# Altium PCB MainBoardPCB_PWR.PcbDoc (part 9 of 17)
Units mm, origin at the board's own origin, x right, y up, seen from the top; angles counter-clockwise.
Board outline 333.63 x 349.38 mm, 16 copper layers (L1, L2 (GND), L3 (Sign), L4 (GND), L5 (Sign), L6 (PWR/GND), L7(PWR/GND), L8 (PWR/GND), L9 (PWR/GND), L10 (PWR/GND), L11 (PWR/GND), L12 (Sign), L13 (GND), L14 (Sign), L15 (GND), L16), stack 2.503 mm thick; 2187 components, 1615 nets, 7987 pads, 1695 vias.
Unrouted connection lines stored in the file: 4757.
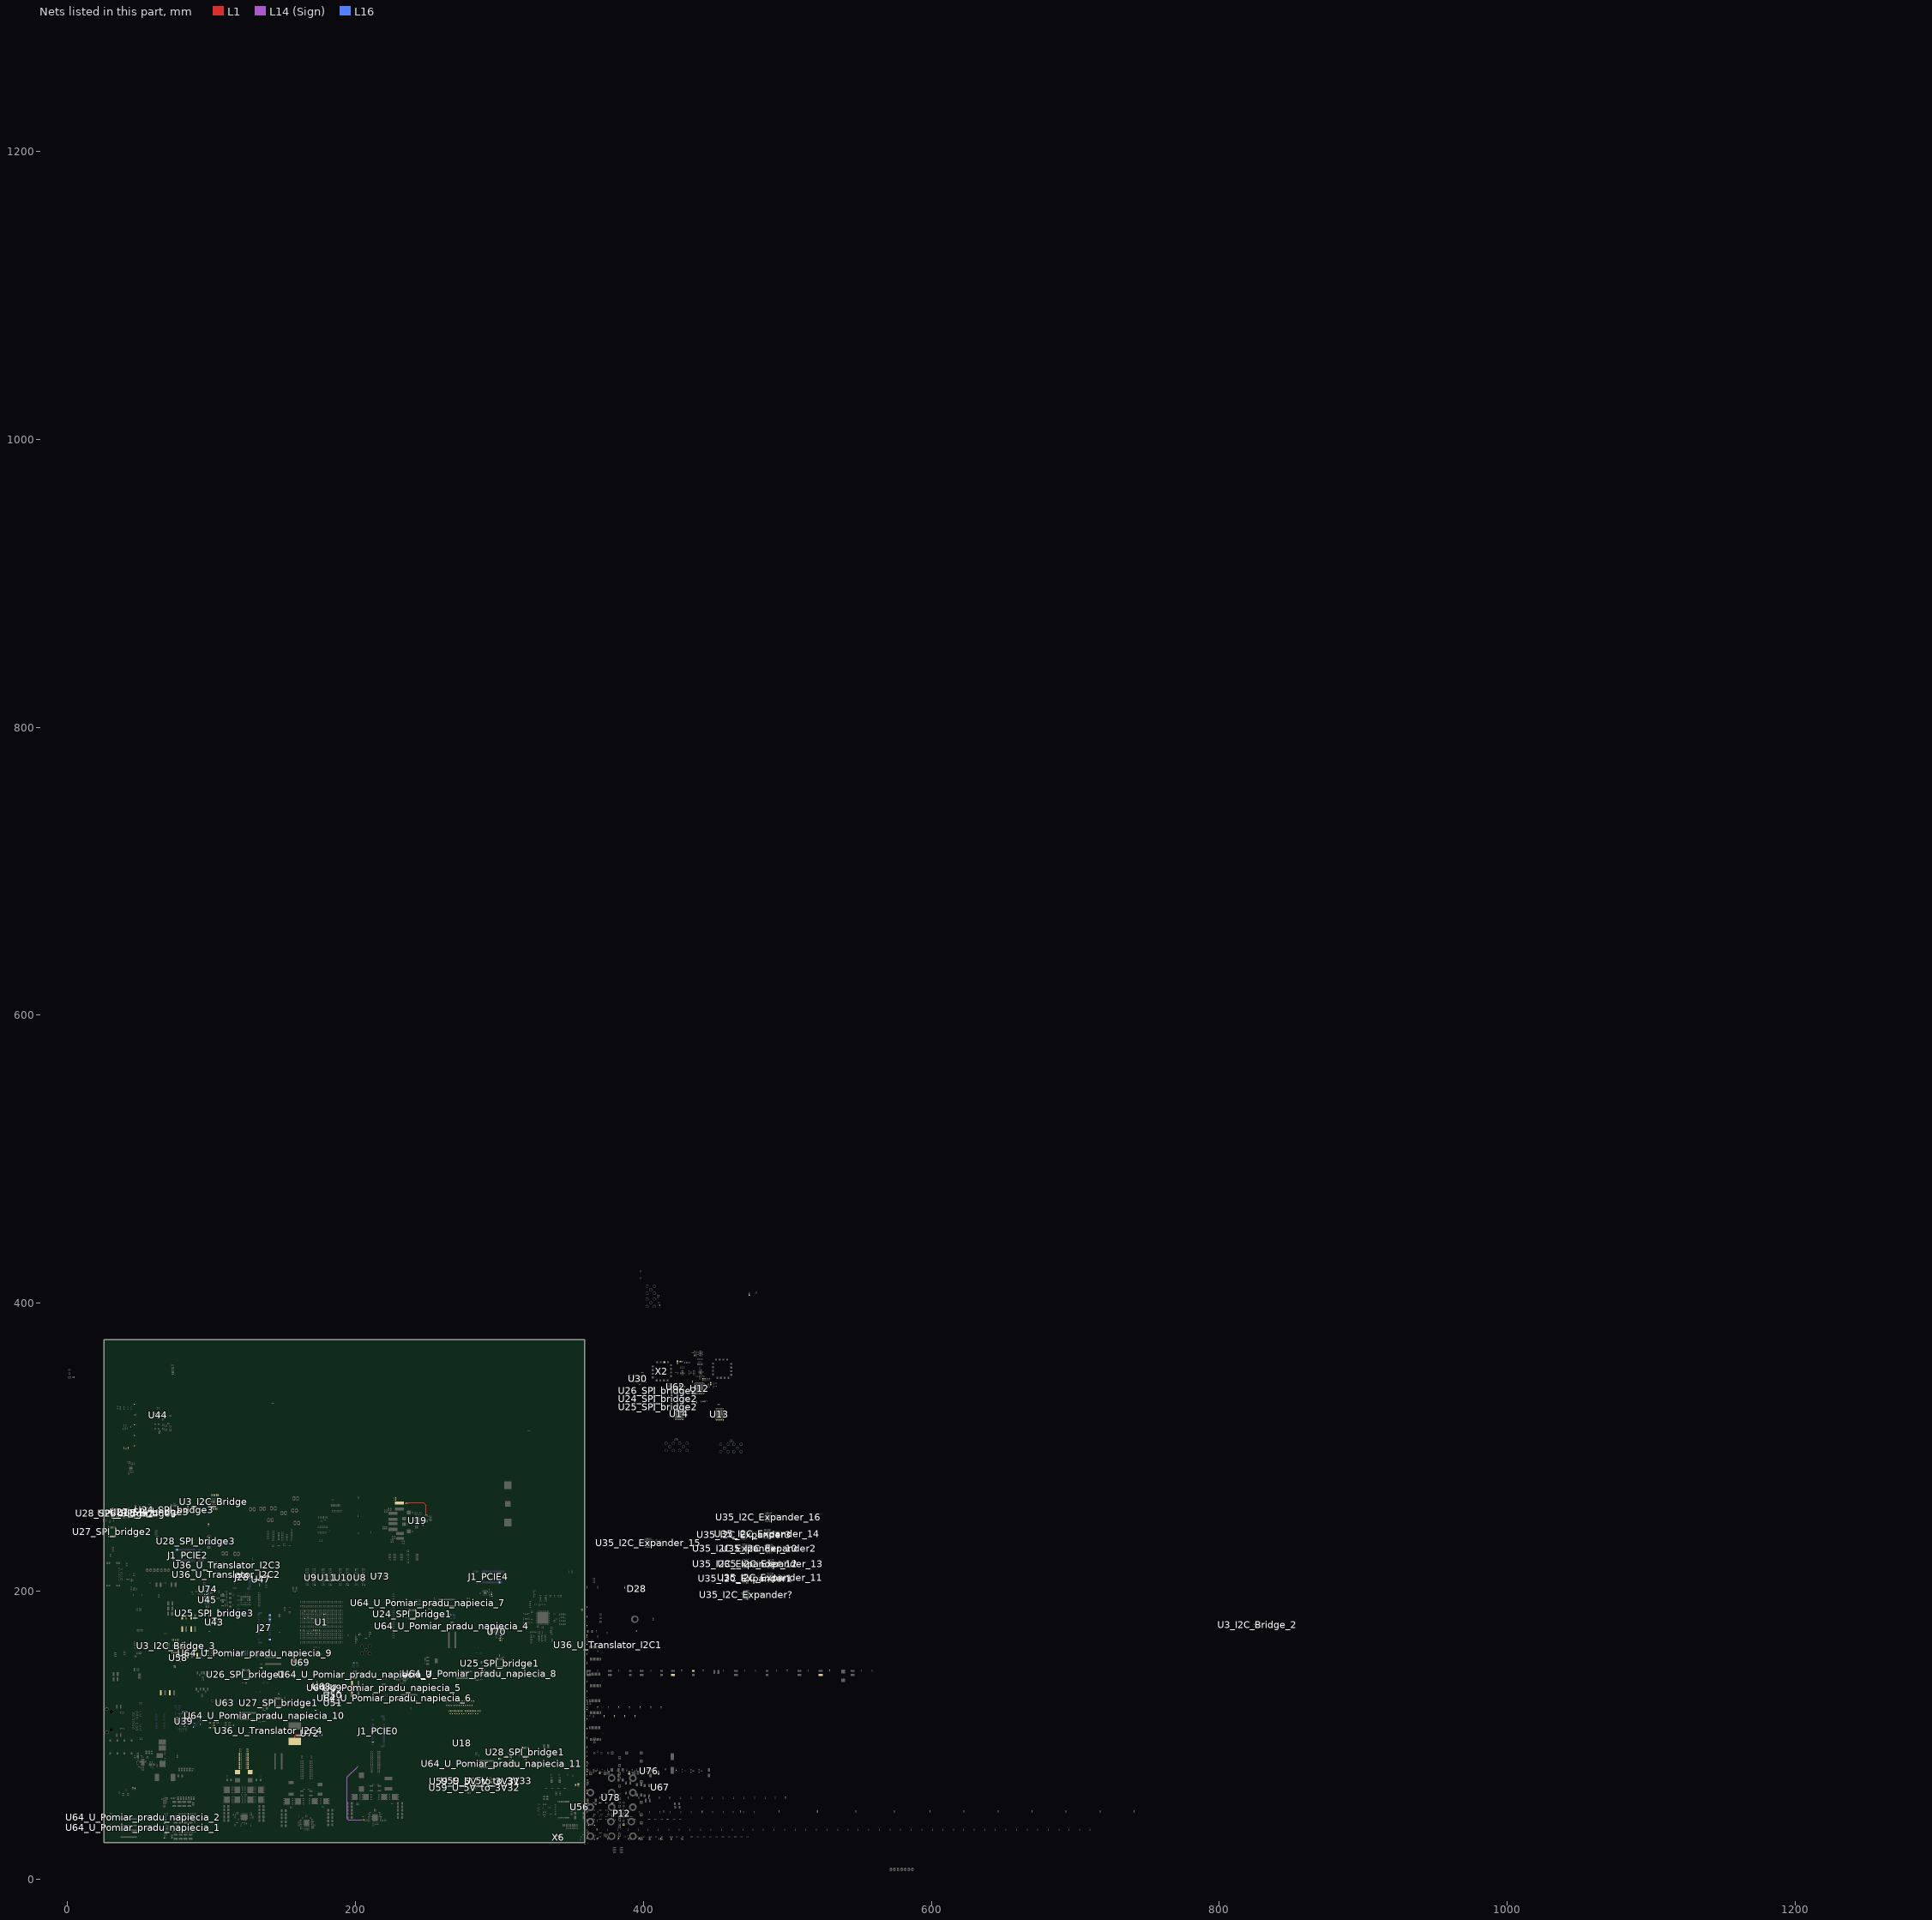
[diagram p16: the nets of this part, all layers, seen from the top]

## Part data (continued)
R600 R601: library part Resistor, Case Code (Imperial)=0402, Case Code (Metric)=1005, Manufacturer=Yageo, Manufacturer Part Number=RC0402JR-070RL, Max Operating Temperature=155°C, Max Power Dissipation=63mW, Min Operating Temperature=-55°C, Package Quantity=1, Power Rating=62.5mW, Supplier Part Number 1=311-0.0JRCT-ND, Temperature Coefficient=200ppm/°C, Tolerance=5%, Voltage Rating=50V
R602 R603 R604 R605 R606 R608 R609: library part Resistor, "RES 10K OHM 0.1% 1/16W 0402", Case/Package=0402, Case Code (Metric)=1005, Manufacturer="Stackpole Electronics", Manufacturer Part Number=RNCF0402BTE10K0, Max Operating Temperature=155°C, Max Power Dissipation=63mW, Min Operating Temperature=-55°C, Package Quantity=10000, Supplier Part Number 1=RNCF0402BTE10K0CT-ND, Temperature Coefficient=25ppm/°C, Tolerance=0.1%
R610 R611: library part Resistor, Case/Package=0402, Case Code (Metric)=1005, Manufacturer=Yageo, Manufacturer Part Number=RC0402FR-071K33L, Max Operating Temperature=155°C, Max Power Dissipation=63mW, Min Operating Temperature=-55°C, Package Quantity=1, Power Rating=62.5mW, Supplier Part Number 1=311-1.33KLRCT-ND, Temperature Coefficient=100ppm/°C, Tolerance=1%, Voltage Rating=50V
R612 R614: library part Resistor, Case/Package=0402, Manufacturer="Vishay BCcomponents", Manufacturer Part Number=MCS04020C2203FE000, Max Operating Temperature=125°C, Min Operating Temperature=-55°C, Supplier Part Number 1=749-1566-1-ND, Temperature Coefficient=50ppm/°C, Tolerance=1%
R613 R616: library part Resistor, Case/Package=1206, Case Code (Metric)=3216, Manufacturer="Vishay Dale", Manufacturer Part Number=CRCW12062R40FKEAHP, Max Operating Temperature=155°C, Max Power Dissipation=500mW, Min Operating Temperature=-55°C, Supplier Part Number 1=541-2.40UCT-ND, Temperature Coefficient=100ppm/°C, Tolerance=1%
R615: library part Resistor, Case/Package=0402, Case Code (Metric)=1005, Manufacturer=Yageo, Manufacturer Part Number=RC0402FR-0710KL, Max Operating Temperature=155°C, Min Operating Temperature=-55°C, Power Rating=62.5mW, Supplier Part Number 1=311-10.0KLRDKR-ND, Temperature Coefficient=100ppm/°C, Tolerance=1%, Voltage Rating=50V
R617: "RES 0.004 OHM 1% 7W 5931", Case/Package=5931, Manufacturer=Yageo, Max Operating Temperature=170°C, Max Power Dissipation=7W, Min Operating Temperature=-65°C, Resistance=4mR, Supplier Part Number 1=YAG4096CT-ND, Temperature Coefficient=75ppm/°C, Tolerance=1%
R619: library part Resistor, Case/Package=0402, Case Code (Metric)=1005, Manufacturer="Stackpole Electronics", Manufacturer Part Number=RMCF0402FT1K91, Max Operating Temperature=155°C, Max Power Dissipation=63mW, Min Operating Temperature=-55°C, Supplier Part Number 1=RMCF0402FT1K91CT-ND, Temperature Coefficient=100ppm/°C, Tolerance=1%
R620: library part Resistor, Case/Package=0402, Case Code (Metric)=1005, Manufacturer=Yageo, Manufacturer Part Number=RC0402FR-072KL, Max Operating Temperature=155°C, Max Power Dissipation=63mW, Min Operating Temperature=-55°C, Package Quantity=1, Supplier Part Number 1=311-2KLRCT-ND, Temperature Coefficient=100ppm/°C, Tolerance=1%, Voltage Rating=50V
R621: library part Resistor, Case/Package=0402, Case Code (Metric)=1005, Manufacturer="Stackpole Electronics", Manufacturer Part Number=RMCF0402FT147K, Max Operating Temperature=155°C, Max Power Dissipation=63mW, Min Operating Temperature=-55°C, Temperature Coefficient=100ppm/°C, Tolerance=1%
R622: library part Resistor, Case/Package=0402, Case Code (Metric)=1005, Manufacturer="Stackpole Electronics", Manufacturer Part Number=RMCF0402FT340K, Max Operating Temperature=155°C, Max Power Dissipation=63mW, Min Operating Temperature=-55°C, Supplier Part Number 1=RMCF0402FT340KCT-ND, Temperature Coefficient=100ppm/°C, Tolerance=1%
R623: library part Resistor, Case/Package=0402, Case Code (Metric)=1005, Manufacturer=Panasonic, Manufacturer Part Number=ERA-2AEB1431X, Max Operating Temperature=155°C, Max Power Dissipation=63mW, Min Operating Temperature=-55°C, Package Quantity=1, Power Rating=62.5mW, Supplier Part Number 1=P1.43KDCCT-ND, Temperature Coefficient=25ppm/°C, Tolerance=0.1%, Voltage Rating=50V
R624: library part Resistor, Case/Package=0402, Case Code (Metric)=1005, Manufacturer=Panasonic, Manufacturer Part Number=ERJ-2RKF1502X, Max Operating Temperature=155°C, Max Power Dissipation=100mW, Min Operating Temperature=-55°C, Package Quantity=1, Supplier Part Number 1=P15.0KLDKR-ND, Temperature Coefficient=100ppm/°C, Tolerance=1%, Voltage Rating=50V
R625: library part Resistor, "Thick Film Resistors - SMD 1.4K OHM 1%", Case/Package=0402, Case Code (Metric)=1005, Manufacturer=Yageo, Manufacturer Part Number=RC0402FR-071K4L, Max Operating Temperature=155°C, Max Power Dissipation=63mW, Min Operating Temperature=-55°C, Power Rating=62.5mW, Supplier Part Number 1=YAG3039CT-ND, Temperature Coefficient=100ppm/°C, Tolerance=1%, Voltage Rating=50V
R626: library part Resistor, Case/Package=0402, Manufacturer="Vishay BCcomponents", Manufacturer Part Number=MCS04020C2003FE000, Max Operating Temperature=125°C, Min Operating Temperature=-55°C, Supplier Part Number 1=749-1562-1-ND, Temperature Coefficient=50ppm/°C, Tolerance=1%
R627: library part Resistor, Case/Package=0402, Case Code (Metric)=1005, Manufacturer=Yageo, Manufacturer Part Number=RC0402FR-0710K5L, Max Operating Temperature=155°C, Max Power Dissipation=63mW, Min Operating Temperature=-55°C, Power Rating=62.5mW, Supplier Part Number 1=YAG2951CT-ND, Temperature Coefficient=100ppm/°C, Tolerance=1%, Voltage Rating=50V
R628: library part Resistor, Case/Package=0402, Case Code (Metric)=1005, Manufacturer="Stackpole Electronics", Manufacturer Part Number=RMCF0402FT750K, Max Operating Temperature=155°C, Max Power Dissipation=63mW, Min Operating Temperature=-55°C, Supplier Part Number 1=RMCF0402FT750KCT-ND, Temperature Coefficient=100ppm/°C, Tolerance=1%
R631: library part Resistor, Case/Package=0402, Case Code (Metric)=1005, Manufacturer="Stackpole Electronics", Manufacturer Part Number=RMCF0402FT5K90, Max Operating Temperature=155°C, Max Power Dissipation=63mW, Min Operating Temperature=-55°C, Supplier Part Number 1=RMCF0402FT5K90CT-ND, Temperature Coefficient=100ppm/°C, Tolerance=1%
R632 R633 R634 R646 R690: library part Resistor, Case/Package=0402, Case Code (Metric)=1005, Manufacturer 1=Panasonic, Manufacturer Part Number 1=ERA-2AED104X, Max Operating Temperature=155°C, Max Power Dissipation=63mW, Min Operating Temperature=-55°C, Package Quantity=10000, Supplier Part Number 1=P100KDECT-ND, Temperature Coefficient=25ppm/°C, Tolerance=0.5%, Voltage Rating=25V
R644: library part Resistor, Case/Package=0402, Case Code (Metric)=1005, Manufacturer=Vishay, Manufacturer Part Number=CRCW04029K10FKED, Max Operating Temperature=155°C, Max Power Dissipation=63mW, Min Operating Temperature=-55°C, Package Quantity=10, Supplier Part Number 1=541-9.10KLCT-ND, Temperature Coefficient=100ppm/°C, Tolerance=1%, Voltage Rating=50V
R645: library part Resistor, Case/Package=0402, Case Code (Metric)=1005, Manufacturer=Panasonic, Manufacturer Part Number=ERA-2AED133X, Max Operating Temperature=155°C, Max Power Dissipation=63mW, Min Operating Temperature=-55°C, Package Quantity=1, Power Rating=62.5mW, Supplier Part Number 1=P13KDECT-ND, Temperature Coefficient=25ppm/°C, Tolerance=0.5%
R647: library part Resistor, "RES SMD 100K OHM 1% 1/16W 0402", Case Code (Imperial)=0402, Case Code (Metric)=1005, Manufacturer=Yageo, Manufacturer Part Number=RC0402FR-07100KL, Max Operating Temperature=155°C, Max Power Dissipation=63mW, Min Operating Temperature=-55°C, Package Quantity=1, Supplier Part Number 1=311-100KLRDKR-ND, Temperature Coefficient=100ppm/°C, Tolerance=1%, Voltage Rating=50V
R648: library part Resistor, "RES SMD 2 OHM 5% 1/16W 0402", Case Code (Imperial)=0402, Case Code (Metric)=1005, Manufacturer=Yageo, Manufacturer Part Number=RC0402JR-072RL, Max Operating Temperature=155°C, Min Operating Temperature=-55°C, Package Quantity=10000, Power Rating=62.5mW, Supplier Part Number 1=311-2.0JRCT-ND, Temperature Coefficient=200ppm/°C, Tolerance=5%, Voltage Rating=50V
R650: library part Resistor, "RES SMD 100M OHM 5% 1/16W 0402", Case Code (Imperial)=0402, Case Code (Metric)=1005, Manufacturer="Stackpole Electronics", Manufacturer Part Number=HMC0402JT100M, Max Operating Temperature=125°C, Max Power Dissipation=63mW, Min Operating Temperature=-55°C, Supplier Part Number 1=HMC0402JT100MCT-ND, Temperature Coefficient=400ppm/°C, Tolerance=5%
R652: library part Resistor, "RES SMD 1M OHM 1% 1/16W 0402", Case Code (Imperial)=0402, Case Code (Metric)=1005, Manufacturer=Yageo, Manufacturer Part Number=RC0402FR-071ML, Max Operating Temperature=155°C, Min Operating Temperature=-55°C, Power Rating=63mW, Supplier Part Number 1=311-1.00MLRDKR-ND, Temperature Coefficient=100ppm/°C, Tolerance=1%, Voltage Rating=50V
R653: library part Resistor, "RES SMD 20 OHM 5% 1/5W 0402", Case Code (Imperial)=0402, Case Code (Metric)=1005, Manufacturer=Rohm, Manufacturer Part Number=ESR01MZPJ200, Max Operating Temperature=155°C, Max Power Dissipation=200mW, Min Operating Temperature=-55°C, Package Quantity=1, Supplier Part Number 1=RHM1011CT-ND, Temperature Coefficient=200ppm/°C, Tolerance=5%
R666: library part Resistor, "RES 0.012 OHM 1% 1/2W 1206", Case/Package=1206, Case Code (Metric)=3216, Manufacturer="Stackpole Electronics", Manufacturer Part Number=CSR1206FK12L0, Max Operating Temperature=155°C, Max Power Dissipation=500mW, Min Operating Temperature=-55°C, Supplier Part Number 1=CSR1206FK12L0CT-ND, Temperature Coefficient=100ppm/°C, Tolerance=1%
R667: library part Resistor, "RES SMD 24.9KOHM 0.1% 1/16W 0402", Case/Package=0402, Case Code (Metric)=1005, Manufacturer=Panasonic, Manufacturer Part Number=ERA-2AEB2492X, Max Operating Temperature=155°C, Max Power Dissipation=63mW, Min Operating Temperature=-55°C, Package Quantity=1, Supplier Part Number 1=P24.9KDCCT-ND, Temperature Coefficient=25ppm/°C, Tolerance=0.1%, Voltage Rating=25V, Voltage Rating (DC)=50V
R671 R673: library part Resistor, Case/Package=0402, Case Code (Metric)=1005, Manufacturer=Panasonic, Manufacturer Part Number=ERA-2AEB1871X, Max Operating Temperature=155°C, Max Power Dissipation=63mW, Min Operating Temperature=-55°C, Package Quantity=10000, Power Rating=62.5mW, Supplier Part Number 1=P1.87KDCCT-ND, Temperature Coefficient=25ppm/°C, Tolerance=0.1%
R672: library part Resistor, Case/Package=0402, Case Code (Metric)=1005, Manufacturer=Panasonic, Manufacturer Part Number=ERA-2AEB152X, Max Operating Temperature=155°C, Max Power Dissipation=63mW, Min Operating Temperature=-55°C, Package Quantity=10000, Supplier Part Number 1=P1.5KDCCT-ND, Temperature Coefficient=25ppm/°C, Tolerance=0.1%, Voltage Rating=25V
R674: library part Resistor, Case/Package=0402, Case Code (Metric)=1005, Manufacturer=Panasonic, Manufacturer Part Number=ERA-2AEB153X, Max Operating Temperature=155°C, Max Power Dissipation=63mW, Min Operating Temperature=-55°C, Package Quantity=1, Supplier Part Number 1=P15KDCCT-ND, Temperature Coefficient=25ppm/°C, Tolerance=0.1%, Voltage Rating=25V
R676: library part Resistor, "RES SMD 20K OHM 1% 1/16W 0402", Case/Package=0402, Case Code (Metric)=1005, Manufacturer=Vishay, Manufacturer Part Number=CRCW040220K0FKED, Max Operating Temperature=155°C, Max Power Dissipation=63mW, Min Operating Temperature=-55°C, Package Quantity=10, Supplier Part Number 1=51X8496, Temperature Coefficient=100ppm/°C, Tolerance=1%, Voltage Rating=50V
R682: library part Resistor, Case/Package=0402, Case Code (Metric)=1005, Manufacturer 1=Yageo, Manufacturer Part Number 1=RC0402FR-077K5L, Max Operating Temperature=155°C, Max Power Dissipation=63mW, Min Operating Temperature=-55°C, Package Quantity=1, Supplier Part Number 1=311-7.50KLRCT-ND, Temperature Coefficient=100ppm/°C, Tolerance=1%, Voltage Rating=50V
R684: library part Resistor, Case/Package=0402, Case Code (Metric)=1005, Manufacturer 1=Yageo, Manufacturer Part Number 1=RC0402FR-077K15L, Max Operating Temperature=155°C, Max Power Dissipation=63mW, Min Operating Temperature=-55°C, Power Rating=62.5mW, Supplier Part Number 1=YAG3235CT-ND, Temperature Coefficient=100ppm/°C, Tolerance=1%, Voltage Rating=50V
R685: library part Resistor, Case/Package=0402, Case Code (Metric)=1005, Manufacturer 1=Yageo, Manufacturer Part Number 1=RC0402FR-075K9L, Max Operating Temperature=155°C, Max Power Dissipation=63mW, Min Operating Temperature=-55°C, Power Rating=62.5mW, Supplier Part Number 1=YAG3197CT-ND, Temperature Coefficient=100ppm/°C, Tolerance=1%, Voltage Rating=50V
R686: library part Resistor, Case/Package=0402, Case Code (Metric)=1005, Manufacturer=Yageo, Manufacturer Part Number=RC0402FR-07412KL, Max Operating Temperature=155°C, Max Power Dissipation=63mW, Min Operating Temperature=-55°C, Power Rating=62.5mW, Supplier Part Number 1=YAG3153CT-ND, Temperature Coefficient=100ppm/°C, Tolerance=1%, Voltage Rating=50V
R687: library part Resistor, Case/Package=0402, Case Code (Metric)=1005, Manufacturer=Panasonic, Manufacturer Part Number=ERA-2AEB5762X, Max Operating Temperature=155°C, Max Power Dissipation=63mW, Min Operating Temperature=-55°C, Package Quantity=1, Power Rating=62.5mW, Supplier Part Number 1=P57.6KDCCT-ND, Temperature Coefficient=25ppm/°C, Tolerance=0.1%, Voltage Rating=50V
R689 R691: library part Resistor, Case/Package=0402, Case Code (Metric)=1005, Manufacturer=Panasonic, Manufacturer Part Number=ERJ-2RKF2002X, Max Operating Temperature=155°C, Max Power Dissipation=100mW, Min Operating Temperature=-55°C, Package Quantity=1, Supplier Part Number 1=P20.0KLCT-ND, Temperature Coefficient=100ppm/°C, Tolerance=1%, Voltage Rating=50V
R695: library part Resistor, Case Code (Imperial)=0402, Case Code (Metric)=1005, Manufacturer=Panasonic, Manufacturer Part Number=ERA-2AEB101X, Max Operating Temperature=155°C, Max Power Dissipation=63mW, Min Operating Temperature=-55°C, Package Quantity=10000, Supplier Part Number 1=P100DCCT-ND, Temperature Coefficient=25ppm/°C, Tolerance=0.1%, Voltage Rating=25V
R737 R746 R747 R748 R749 R750 R751 R752 R753 R754 R755 R756 R757: library part Resistor, "Surface Mount Thick Film Resistor, Rc Series, 10 Kohm, 62.5 Mw, - 1%, 50 V, 0402 [1005 Metric]", Case Code (Imperial)=0402, Case Code (Metric)=1005, Manufacturer=Yageo, Manufacturer Part Number=RC0402FR-0710KL, Max Operating Temperature=155°C, Min Operating Temperature=-55°C, Power Rating=62.5mW, Supplier Part Number 1=311-10.0KLRDKR-ND, Temperature Coefficient=100ppm/°C, Tolerance=1%, Voltage Rating=50V
R764: "RES 0.004 OHM 1% 10W 2818", Case/Package=Nonstandard, Manufacturer=Vishay, Max Operating Temperature=170°C, Max Power Dissipation=10W, Min Operating Temperature=-65°C, Resistance=4mR, Supplier Part Number 1=541-3274-1-ND, Temperature Coefficient=200ppm/°C, Tolerance=1%
R838 R840 R841: library part Resistor, Case Code (Imperial)=0402, Case Code (Metric)=1005, Manufacturer=Panasonic, Manufacturer Part Number=ERJ-2RKF2002X, Max Operating Temperature=155°C, Max Power Dissipation=100mW, Min Operating Temperature=-55°C, Package Quantity=1, Supplier Part Number 1=P20.0KLCT-ND, Temperature Coefficient=100ppm/°C, Tolerance=1%, Voltage Rating=50V
S1 S5: library part "SW DIP-4"
S2 S3 S4 S6 S7: "WS-TASV SMT Tact Switch 4.5x4.5mm, height 3.8mm, 160gf", Operating Temperature="-40 to +85degC", Rated Current=50mA, Rated Voltage=12VDC
T5 T6 T9 T10 T13 T15 T17 T19: "MOSFET N-CH 30V 53A TDSON-8", Continuous Drain Current (ID)=53A, Drain to Source Breakdown Voltage=30V, Drain to Source Resistance=8mR, Gate to Source Voltage (Vgs)=20V, Input Capacitance=1.7nF, Manufacturer 1=Infineon, Max Operating Temperature=150°C, Max Power Dissipation=35W, Min Operating Temperature=-55°C, Package Quantity=1, Power Dissipation=2.5W, Supplier Part Number 1=BSC080N03LSGATMA1CT-ND, Threshold Voltage=2.2V
T7 T8 T11 T12 T14 T16 T18 T20: "MOSFET, N CH, 100A, 30V, PG-TDSON-8", Case/Package=TO-252-3, Continuous Drain Current (ID)=100A, Drain to Source Breakdown Voltage=30V, Drain to Source Resistance=4.7mR, Gate to Source Voltage (Vgs)=20V, Input Capacitance=4.3nF, Manufacturer 1=Infineon, Max Operating Temperature=150°C, Max Power Dissipation=69W, Min Operating Temperature=-55°C, Package Quantity=5000, Power Dissipation=2.5W, Supplier Part Number 1="BSC030N03LS G-ND", Threshold Voltage=1V
T21: "WE-RJ45 LAN Transformer, THT, 10/100/1000 Base-T, Port 1x1, Tab Up", Operating Temperature="-40 to +85degC"
T22 T23 T27 T30: "MOSFET MOSFT P-Ch -4.3A 50mOhm 10nC Log Lvl", Case/Package=SOT-23, Continuous Drain Current (ID)=4.3A, Current Rating=-4.3A, Drain to Source Breakdown Voltage=-12V, Drain to Source Resistance=50mR, Drain to Source Voltage (Vdss)=12V, Gate to Source Voltage (Vgs)=8V, Input Capacitance=830pF, Manufacturer="International Rectifier", Max Operating Temperature=150°C, Max Power Dissipation=1.3W, Min Operating Temperature=-55°C, Package Quantity=1, Supplier Part Number 1=IRLML6401PBFCT-ND, Threshold Voltage=-550mV
T24 T25 T26 T28 T29 T31 T36: "Trans MOSFET N-CH 8V 6A 3-Pin SOT-23 T/R", Case/Package=SOT-23, Continuous Drain Current (ID)=6A, Drain to Source Voltage (Vdss)=8V, Gate to Source Voltage (Vgs)=5V, Input Capacitance=1.07nF, Manufacturer=Vishay, Max Operating Temperature=150°C, Max Power Dissipation=2.5W, Min Operating Temperature=-55°C, Package Quantity=3000, Power Dissipation=1.3W, Supplier Part Number 1=SI2342DS-T1-GE3CT-ND, Threshold Voltage=800mV
T34: "MOSFET N-CH 60V 25A LFPAK", Continuous Drain Current (ID)=25A, Drain to Source Resistance=14MR, Drain to Source Voltage (Vdss)=60V, Gate to Source Voltage (Vgs)=20V, Input Capacitance=2.03nF, Manufacturer=Renesas, Max Operating Temperature=150°C, Max Power Dissipation=45W, Min Operating Temperature=-55°C, Package Quantity=1, Supplier Part Number 1=968-RJK0651DPB-00#J5
T35: "MOSFET 80V 6.2mOhm@10V 60A N-Ch MV T-FET", Continuous Drain Current (ID)=60A, Drain to Source Breakdown Voltage=80V, Drain to Source Resistance=6.2mR, Gate to Source Voltage (Vgs)=20V, Input Capacitance=2.425nF, Manufacturer=Vishay, Max Operating Temperature=150°C, Max Power Dissipation=69.4W, Min Operating Temperature=-55°C, On-State Resistance=9.5MR, Package Quantity=1, Supplier Part Number 1=SIJ482DP-T1-GE3CT-ND, Threshold Voltage=1.5V
TP1_I2C_Bridge TP1_I2C_Bridge_2 TP1_I2C_Bridge_3 TP2_I2C_Bridge TP2_I2C_Bridge_2 TP2_I2C_Bridge_3 TP3_I2C_Bridge TP3_I2C_Bridge_2 TP3_I2C_Bridge_3 TP4_I2C_Bridge TP4_I2C_Bridge_2 TP4_I2C_Bridge_3 TP5_I2C_Bridge TP5_I2C_Bridge_2 TP5_I2C_Bridge_3 TP6_I2C_Bridge TP6_I2C_Bridge_2 TP6_I2C_Bridge_3 TP7_I2C_Bridge TP7_I2C_Bridge_2 TP7_I2C_Bridge_3 TP8_I2C_Bridge TP8_I2C_Bridge_2 TP8_I2C_Bridge_3 TP9_I2C_Bridge TP9_I2C_Bridge_2 TP9_I2C_Bridge_3 TP10_I2C_Bridge TP10_I2C_Bridge_2 TP10_I2C_Bridge_3 TP11_I2C_Bridge TP11_I2C_Bridge_2 TP11_I2C_Bridge_3 TP12_I2C_Bridge TP12_I2C_Bridge_2 TP12_I2C_Bridge_3 TP13_I2C_Bridge TP13_I2C_Bridge_2 TP13_I2C_Bridge_3 TP14_I2C_Bridge TP14_I2C_Bridge_2 TP14_I2C_Bridge_3 TP15_I2C_Bridge TP15_I2C_Bridge_2 TP15_I2C_Bridge_3 TP16_I2C_Bridge TP16_I2C_Bridge_2 TP16_I2C_Bridge_3 TP17_I2C_Bridge TP17_I2C_Bridge_2 TP17_I2C_Bridge_3 TP18_I2C_Bridge TP18_I2C_Bridge_2 TP18_I2C_Bridge_3 TP19 TP20 TP21 TP22 TP23 TP24 TP25 TP26 TP27 TP28 TP29 TP30 TP31 TP32 TP33 TP34 TP35 TP36 TP37 TP38 TP39 TP40 TP41 TP42 TP43 TP44 TP45 TP46 TP47 TP48 TP49 TP50_SPI_bridge1 TP50_SPI_bridge2 TP50_SPI_bridge3 TP51_SPI_bridge1 TP51_SPI_bridge2 TP51_SPI_bridge3 TP52_SPI_bridge1 TP52_SPI_bridge2 TP52_SPI_bridge3 TP53_SPI_bridge1 TP53_SPI_bridge2 TP53_SPI_bridge3 TP54_SPI_bridge1 TP54_SPI_bridge2 TP54_SPI_bridge3 TP55_SPI_bridge1 TP55_SPI_bridge2 TP55_SPI_bridge3 TP56_SPI_bridge1 TP56_SPI_bridge2 TP56_SPI_bridge3 TP57_SPI_bridge1 TP57_SPI_bridge2 TP57_SPI_bridge3 TP58_SPI_bridge1 TP58_SPI_bridge2 TP58_SPI_bridge3 TP59_SPI_bridge1 TP59_SPI_bridge2 TP59_SPI_bridge3 TP60_U_Translator_I2C1 TP60_U_Translator_I2C2 TP60_U_Translator_I2C3 TP60_U_Translator_I2C4 TP61_U_Translator_I2C1 TP61_U_Translator_I2C2 TP61_U_Translator_I2C3 TP61_U_Translator_I2C4 TP62 TP63 TP64 TP65 TP66 TP67 TP68 TP69 TP70 TP71 TP72 TP73 TP74 TP75 TP76 TP77 TP78 TP79 TP80 TP81 TP82 TP83 TP84 TP85 TP86 TP87 TP88 TP91 TP92: "TEstPoint", Color=Black, Flammability Rating="UL94 V-0", Manufacturer="Keystone Electronics", Manufacturer Part Number=5001, Package Quantity=100, Supplier Part Number 1=36-5001-ND
U1: "FPGA Zynq UltraScale+ Family 192150 Cells 20nm Technology 0.85V 900-Pin FCBGA Tray", Case/Package=FCBGA, Frequency=500MHz, Manufacturer=Xilinx, Manufacturer Part Number=XCZU4CG-1FBVB900E, Max Operating Temperature=100°C, Min Operating Temperature=0°C, Supplier Part Number 1=217-CZU4CG-1FBVB900E
U3_I2C_Bridge U3_I2C_Bridge_2 U3_I2C_Bridge_3: "8X I2C Switch", Case/Package=VQFN, Manufacturer="Texas Instruments", Manufacturer Part Number=TCA9548ARGER, Max Operating Temperature=85°C, Max Supply Current=80uA, Max Supply Voltage=5.5V, Min Operating Temperature=-40°C, Min Supply Voltage=1.65V, On-State Resistance=70R, Package Quantity=3000, Supplier Part Number 1=296-39222-1-ND
U4 U5 U48: Manufacturer 1="Texas Instruments", Supplier Part Number 1=296-53412-1-ND
U6 U7 U17 U18 U20 U21 U22 U23 U46: "Current Limit Load Switch with OVP and TRCB, 28 V, 5 A", Manufacturer 1="ON Semiconductor", Supplier Part Number 1=863-FPF2895CUCX
U8 U9 U10 U11: "RAM 8GB", Frequency=1.2GHz, Manufacturer="Micron Technology", Manufacturer Part Number=MT40A512M16JY-083EIT:BTR, Max Operating Temperature=95°C, Min Operating Temperature=-40°C, Supplier Part Number 1=557-1690-2-ND
U12 U13 U14: "Dystrybutor Zegarów", Manufacturer="Analog Devices", Manufacturer Part Number=LTC6952IUKG#PBF, Supplier Part Number 1=LTC6952IUKG#PBF-ND
U15 U24_SPI_bridge1 U24_SPI_bridge2 U24_SPI_bridge3 U25_SPI_bridge1 U25_SPI_bridge2 U25_SPI_bridge3 U26_SPI_bridge1 U26_SPI_bridge2 U26_SPI_bridge3 U27_SPI_bridge1 U27_SPI_bridge2 U27_SPI_bridge3 U28_SPI_bridge1 U28_SPI_bridge2 U28_SPI_bridge3 U43 U53 U56 U57 U79: Manufacturer 1="Texas Instruments", Supplier Part Number 1=296-SN74AXC4T774PWRCT-ND
U16: Manufacturer="Texas Instruments", Manufacturer Part Number=LMK05028RGCR, Supplier Part Number 1=296-49099-1-ND
U19: "Quad 40 V / 1 A Step-Down Switching Regulator with 100% Duty Cycle Operation, 28-pin QFN (UFD-28), -40 to 125 degC, Pb-Free", Manufacturer="Linear Technology", Supplier Part Number 1=LT3504EUFD#PBF-ND
U30: "DAC 20bit", Case/Package=SSOP, Manufacturer="Texas Instruments", Manufacturer Part Number=DAC1220E, Max Operating Temperature=85°C, Max Supply Voltage=5.25V, Min Operating Temperature=-40°C, Min Supply Voltage=4.75V, Nominal Supply Current=460uA, Operating Supply Voltage=5V, Package Quantity=75, Power Consumption=2.5mW, Supplier Part Number 1=DAC1220E-ND
U31 U32: "IC BUFFER 2:4 LVPECL MUX 16QFN", Case/Package=QFN, Frequency=1.25GHz, Manufacturer 1="Silicon Labs", Max Operating Temperature=85°C, Max Supply Voltage=3.63V, Min Operating Temperature=-40°C, Min Supply Voltage=2.38V, Nominal Supply Current=210mA, Package Quantity=100, Supplier Part Number 1=336-2500-5-ND
U33: "IC, BUF LVPECL CLOCK DRVR 16-VQFN", Case/Package=QFN, Frequency=800MHz, Input Current=10uA, Manufacturer="Texas Instruments", Max Operating Temperature=85°C, Max Supply Voltage=3.6V, Min Operating Temperature=-40°C, Min Supply Voltage=3V, Package Quantity=1, Supplier Part Number 1=296-17045-1-ND
U34 U37 U38: "Analog Devices", Case/Package="LFCSP EP", Max Input Voltage=20V, Max Operating Temperature=85°C, Max Output Current=30A, Min Input Voltage=2.75V, Min Operating Temperature=-40°C, Nominal Supply Current=4.5mA, Operating Supply Current=100uA, Output Current=25A, Output Voltage=18V, Supplier Part Number 1=ADP1850ACPZ-R7CT-ND, Switching Frequency=1.5MHz
U35_I2C_Expander1 U35_I2C_Expander2 U35_I2C_Expander3 U35_I2C_Expander? U35_I2C_Expander_10 U35_I2C_Expander_11 U35_I2C_Expander_12 U35_I2C_Expander_13 U35_I2C_Expander_14 U35_I2C_Expander_15 U35_I2C_Expander_16: "16-Bit I/O Expander with Serial Interface, 28-Pin QFN, Extended Temperature", Manufacturer=Microchip, Supplier Part Number 1=MCP23017-E/ML-ND
U36_U_Translator_I2C1 U36_U_Translator_I2C2 U36_U_Translator_I2C3 U36_U_Translator_I2C4: "I2C [V] Level translator", Low Level Output Current=128mA, Manufacturer="Texas Instruments", Manufacturer Part Number=PCA9306DQER, Max Operating Temperature=85°C, Max Supply Voltage=5V, Min Operating Temperature=-40°C, Min Supply Voltage=0uV, Package Quantity=1, Supplier Part Number 1=296-27957-1-ND
U39: "IC ETHERNET PHY 48VQFN", Case/Package=VQFN, Manufacturer 1="Texas Instruments", Max Operating Temperature=105°C, Max Supply Voltage=2.625V, Min Operating Temperature=-40°C, Min Supply Voltage=950mV, Supplier Part Number 1=296-43254-1-ND
U40 U42 U49 U50 U51 U59_5V_to_3V3_for_FTDI U59_U_5V_to_3V31 U59_U_5V_to_3V32 U59_U_5V_to_3V33: "IC REG LDO ADJ 1.5A 8DFN", Case/Package=DFN, Dropout Voltage=330mV, Input Bias Current=120uA, Manufacturer 1=Microchip, Max Input Voltage=6V, Max Operating Temperature=125°C, Max Output Current=1.5A, Min Input Voltage=2.3V, Min Operating Temperature=-40°C, Output Voltage=5V, Package Quantity=3300, Reference Voltage=410mV, Supplier Part Number 1=MCP1727T-ADJE/MFCT-ND
U41: "IC FLASH 64G MMC", Manufacturer 1="Micron Technology", Supplier Part Number 1=340-296563-REEL
U44: "IC SUPERVISORY CIRC DL 16TQFN", Manufacturer=Maxim, Max Operating Temperature=125°C, Max Power Dissipation=2W, Max Supply Voltage=28V, Min Operating Temperature=-40°C, Min Supply Voltage=2.2V, Number of Voltages Monitored=2, Operating Supply Current=52uA, Package Quantity=2500, Supplier Part Number 1=MAX16025TE+TCT-ND
U45: "IC TXRX USB 2.0 FLEXPWR 32QFN", Case/Package=QFN, Frequency=60MHz, Manufacturer 1=Microchip, Max Operating Temperature=85°C, Min Operating Temperature=-40°C, Operating Supply Current=18uA, Operating Supply Voltage=5.5V, Package Quantity=4000, Supplier Part Number 1=USB3320C-EZK-DKR-ND
U47: "Memory Card Interface 25-WLCSP (2.04x2.04)", Manufacturer 1="Nexperia USA", Supplier Part Number 1=1727-8607-1-ND
U54: "MICROCHIP - 93LC56BT-I/OT. - 2K, 128 X 16, SERIAL EE, IND ROHS COMPLIANT: YES", Case/Package=SOT-23, Frequency=2MHz, Manufacturer=Microchip, Max Operating Temperature=85°C, Max Supply Voltage=5.5V, Min Operating Temperature=-40°C, Min Supply Voltage=2.5V, Nominal Supply Current=2mA, Package Quantity=3000, Supplier Part Number 1=93LC56BT-I/OTCT-ND
U55: "IC USB HS QUAD UART/SYNC 64-LQFP", Case/Package=LQFP, Dual Supply Voltage=3.3V, Manufacturer 1=FTDI, Max Operating Temperature=85°C, Max Supply Voltage=3.63V, Min Operating Temperature=-40°C, Min Supply Voltage=1.62V, Operating Supply Current=70mA, Package Quantity=1000, Supplier Part Number 1=768-1026-1-ND
U58: Manufacturer 1=STMicroelectronics, Supplier Part Number 1=497-19784-1-ND
U60 U69: "IC REG LIN POS ADJ 2A 16LFCSP", Case/Package="LFCSP EP", Dropout Voltage=160mV, Manufacturer="Analog Devices", Max Input Voltage=3.6V, Max Operating Temperature=125°C, Max Output Current=2A, Max Output Voltage=3V, Max Supply Current=1.8mA, Min Current Limit=2.4A, Min Input Voltage=1.6V, Min Operating Temperature=-40°C, Min Output Voltage=750mV, Output Voltage Accuracy=1%, Power Supply Rejection Ratio (PSRR)=70dB, Supplier Part Number 1=ADP1741ACPZ-R7CT-ND
U61 U70: "IC REG LINEAR POS ADJ 1A 20QFN", Case/Package=QFN, Dropout Voltage=130mV, Manufacturer="Texas Instruments", Max Operating Temperature=125°C, Min Current Limit=1.5A, Min Operating Temperature=-40°C, Output Current=1A, Output Voltage=5V, Quiescent Current=2mA, Supplier Part Number 1=296-43312-1-ND
U62: "LINEAR TECHNOLOGY         LT3042EDD#PBF             LDO Voltage Regulator, Adjustable, 1.8V to 20V in, 350mV drop, 0V to 15V/0.2A out, DFN-10", Case/Package=DFN, Dropout Voltage=350mV, Manufacturer="Analog Devices / Linear Technology", Max Input Voltage=20V, Max Operating Temperature=125°C, Max Output Voltage=15V, Min Current Limit=220mA, Min Input Voltage=1.8V, Min Operating Temperature=-40°C, Min Output Voltage=0uV, Output Current=200mA, Supplier Part Number 1=LT3042EDD#PBF-ND
U63: "IC TXRX CAN 1MBPS SOT23-8", Case/Package=SOT-23-8, Manufacturer=Maxim, Max Operating Temperature=85°C, Max Supply Current=70mA, Max Supply Voltage=3.465V, Min Operating Temperature=-40°C, Min Supply Voltage=3.135V, Operating Supply Current=35mA, Operating Supply Voltage=3.3V, Package Quantity=1, Supplier Part Number 1=MAX3051EKA+TCT-ND
U64_U_Pomiar_pradu_napiecia_1 U64_U_Pomiar_pradu_napiecia_2 U64_U_Pomiar_pradu_napiecia_3 U64_U_Pomiar_pradu_napiecia_4 U64_U_Pomiar_pradu_napiecia_5 U64_U_Pomiar_pradu_napiecia_6 U64_U_Pomiar_pradu_napiecia_7 U64_U_Pomiar_pradu_napiecia_8 U64_U_Pomiar_pradu_napiecia_9 U64_U_Pomiar_pradu_napiecia_10 U64_U_Pomiar_pradu_napiecia_11 U72: "IC MONITOR PWR/CURR BIDIR 10MSOP", Case/Package=VSSOP, Input Bias Current=10uA, Input Offset Voltage (Vos)=2.5uV, Manufacturer="Texas Instruments", Max Operating Temperature=125°C, Max Supply Voltage=5.5V, Min Operating Temperature=-40°C, Min Supply Voltage=2.7V, Nominal Supply Current=330uA, Output Current=10mA, Package Quantity=1, Supplier Part Number 1=296-29034-1-ND
U65: "IC REG CTRLR BUCK 20-TQFN", Manufacturer=Maxim, Supplier Part Number 1=MAX17557ATP+-ND
U67 U68: "IC PWR SUPPLY SEQUENCER SOT23-6", Case/Package=SOT-23-6, Manufacturer="TI National Semiconductor", Max Operating Temperature=125°C, Max Supply Voltage=5.5V, Min Operating Temperature=-40°C, Min Supply Voltage=2.7V, Number of Voltages Monitored=3, Operating Supply Current=25uA, Overvoltage Threshold=1.4V, Package Quantity=250, Supplier Part Number 1=LM3880MFE-1AF/NOPBCT-ND, Undervoltage Threshold=1V
U71: "IC REG LINEAR 8V 500MA SOT223-4", Case/Package=SOT-223-4, Dropout Voltage=2V, Manufacturer="Texas Instruments", Max Input Voltage=25V, Max Operating Temperature=125°C, Max Output Current=500mA, Min Input Voltage=10.5V, Min Operating Temperature=-40°C, Nominal Output Voltage=8V, Package Quantity=1, Power Supply Rejection Ratio (PSRR)=80dB, Quiescent Current=4.6mA, Supplier Part Number 1=296-12612-1-ND
U73: "IC REG LINEAR POS ADJ 800MA 8DFN", Case/Package=DFN, Dropout Voltage=700mV, Input Bias Current=150uA, Manufacturer=STMicroelectronics, Max Input Voltage=5.5V, Max Operating Temperature=125°C, Max Output Current=800mA, Min Input Voltage=1V, Min Operating Temperature=-40°C, Operating Supply Current=200nA, Output Voltage=4V, Package Quantity=2500, Power Supply Rejection Ratio (PSRR)=80dB, Supplier Part Number 1=497-15098-1-ND, Tolerance=2%
U74 U76: "IC GATE AND 1CH 2-INP SOT23-5", Case/Package=SOT-23, High Level Output Current=-32mA, Low Level Output Current=32mA, Manufacturer="Texas Instruments", Max Operating Temperature=125°C, Max Supply Voltage=5.5V, Min Operating Temperature=-40°C, Min Supply Voltage=1.65V, Package Quantity=1, Quiescent Current=10uA, Supplier Part Number 1=296-11601-1-ND
U75: "TVS DIODE 26.5VWM 44VC SOT323", Case/Package=SOT-323-3, Clamping Voltage=44V, Manufacturer=STMicroelectronics, Max Operating Temperature=175°C, Min Breakdown Voltage=28.5V, Min Operating Temperature=-55°C, Peak Pulse Current=3A, Peak Pulse Power=250W, Power Line Protection=No, Reverse Standoff Voltage=26.5V, Supplier Part Number 1=497-15845-1-ND
U77 U78: "Buffer/Driver 2-CH Non-Inverting Open Drain CMOS 6-Pin MicroPak T/R", Low Level Output Current=32mA, Manufacturer="ON Semiconductor / Fairchild", Max Operating Temperature=85°C, Max Supply Voltage=5.5V, Min Operating Temperature=-40°C, Min Supply Voltage=1.65V, Package Quantity=5000, Quiescent Current=1uA, Supplier Part Number 1=NC7WZ07FHXCT-ND
X1: library part CVCO55CC-2000-2000, Frequency=2GHz, Load Capacitance=22pF, Manufacturer=Crystek, Max Operating Temperature=85°C, Min Operating Temperature=-30°C, Operating Supply Voltage=8V, Package Quantity=1, Supplier Part Number 1=549-CVCO55CC20002000
X2: library part CVCO55CL-0490-0540, Case/Package=SMD/SMT, Frequency=540MHz, Load Capacitance=100pF, Manufacturer=Crystek, Max Operating Temperature=85°C, Max Supply Voltage=5.25V, Min Operating Temperature=-40°C, Min Supply Voltage=4.75V, Package Quantity=5, Supplier Part Number 1=744-1174-ND
X3: library part MP024S, "CRYSTAL 2.4576MHZ 32PF T/H", ESR (Equivalent Series Resistance)=300R, Frequency Stability=50ppm, Frequency Tolerance=30ppm, Load Capacitance=32pF, Manufacturer=CTS, Max Operating Temperature=70°C, Min Operating Temperature=-20°C, Package Quantity=100, Supplier Part Number 1=CTX069-ND
X4: "CRYSTAL 25.0000MHZ 18PF SMD", Case/Package=SMD/SMT, ESR (Equivalent Series Resistance)=50R, Frequency=25MHz, Frequency Stability=30ppm, Frequency Tolerance=50ppm, Load Capacitance=18pF, Manufacturer 1=Epson, Max Operating Temperature=70°C, Min Operating Temperature=-20°C, Package Quantity=250, Supplier Part Number 1=SER3691CT-ND
X5: library part FC-13532.7680KA-A5, "CRYSTAL 32.7680 KHZ 12.5PF SMD", Case/Package=SMD/SMT, ESR (Equivalent Series Resistance)=70kR, Frequency Tolerance=20ppm, Load Capacitance=12.5pF, Manufacturer=Epson, Max Operating Temperature=85°C, Min Operating Temperature=-40°C, Supplier Part Number 1=SER4103CT-ND
X6: "SMD Crystal Oscillator 50MHz 3.3V 4-Pin SMD Tray", Case/Package=SMD/SMT, Frequency=50MHz, Frequency Stability=20ppm, Manufacturer="Silicon Labs", Operating Supply Voltage=3.3V, Package Quantity=1, Supplier Part Number 1=336-5245-ND
X7: "CRYSTAL 24.00 MHZ 9.0PF SMD", Case/Package=SMD/SMT, ESR (Equivalent Series Resistance)=40R, Frequency=24MHz, Frequency Stability=15ppm, Frequency Tolerance=10ppm, Load Capacitance=9pF, Manufacturer 1=Epson, Max Operating Temperature=85°C, Min Operating Temperature=-40°C, Supplier Part Number 1=SER4180DKR-ND
X8: Manufacturer 1="ECS International", Supplier Part Number 1=XC2904CT-ND
X9: "OSC MEMS 48.0000MHZ LVCMOS SMD", Case/Package=SMD/SMT, Frequency=48MHz, Frequency Stability=25ppm, Manufacturer=SiTime, Max Operating Temperature=85°C, Max Supply Current=4.5mA, Min Operating Temperature=-40°C, Supplier Part Number 1=1473-30890-1-ND

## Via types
v1: diameter 0.5, hole 0.2, L1 to L16, 786 vias
v2: diameter 0.5/0.35/0.35/0.35/0.35/0.35/0.35/0.35/0.35/0.35/0.35/0.35/0.35/0.35/0.35/0.5 (per signal layer), hole 0.15, L1 to L16, tented both sides, 164 vias
v3: diameter 2.54, hole 1.02, L1 to L16, 152 vias
v4: diameter 0.5/0.35/0.35/0.35/0.35/0.35/0.35/0.35/0.35/0.35/0.35/0.35/0.35/0.35/0.35/0.5 (per signal layer), hole 0.2, L1 to L16, tented both sides, 100 vias
v5: diameter 0.45, hole 0.15, L1 to L16, 79 vias
v6: diameter 0.35/0/0.35 (per signal layer), hole 0.127, L1 to L3 (Sign), tented both sides, 78 vias
v7: diameter 0.45/0.45/0.45/0.45/0.45/0.45/0.45/0.45/0.45/0.45/0.45/0.45/0.45/0.45/0.45/0.45 (per signal layer), hole 0.15, L1 to L16, 65 vias
v8: diameter 0.4, hole 0.15, L1 to L16, 61 vias
v9: diameter 0.2, hole 0.1, L1 to L16, 35 vias
v10: diameter 0.5, hole 0.2, L1 to L16, tented both sides, 32 vias
v11: diameter 0.2/0/0.2 (per signal layer), hole 0.1, L1 to L3 (Sign), 28 vias
v12: diameter 0.4, hole 0.2, L1 to L16, 16 vias
v13: diameter 0.25, hole 0.2, L1 to L16, 16 vias
v14: diameter 0.3, hole 0.2, L1 to L16, 15 vias
v15: diameter 0.5/0.35/0.35/0.35/0.35/0.35/0.35/0.35/0.35/0.35/0.35/0.35/0.35/0.35/0.35/0.45 (per signal layer), hole 0.15, L1 to L16, tented both sides, 10 vias
v16: diameter 5, hole 3, L1 to L16, 9 vias
v17: diameter 0.2/0/0.2 (per signal layer), hole 0.1, L1 to L3 (Sign), tented both sides, 9 vias
v18: diameter 0.35/0/0.35 (per signal layer), hole 0.127, L1 to L3 (Sign), 7 vias
v19: diameter 0.35/0/0.35 (per signal layer), hole 0.127, L14 (Sign) to L16, tented both sides, 5 vias
v20: diameter 1.65, hole 1.65, L1 to L16, 4 vias
v21: diameter 1.15, hole 1.15, L1 to L16, 4 vias
v22: diameter 0.35, hole 0.127, L1 to L2 (GND), 2 vias
v23: diameter 0.4, hole 0.2, L1 to L16, tented both sides, 2 vias
v24: diameter 0.35, hole 0.127, L1 to L2 (GND), tented both sides, 2 vias
v25: diameter 0.508, hole 0.127, L1 to L2 (GND), 2 vias
v26: diameter 0.508, hole 0.127, L2 (GND) to L3 (Sign), 2 vias
v27: diameter 0.35, hole 0.127, L3 (Sign) to L6 (PWR/GND), tented both sides, 2 vias
v28: diameter 0.5, hole 0.2, L3 (Sign) to L6 (PWR/GND), tented both sides, 2 vias
v29: diameter 5.5, hole 3.5, L1 to L16, 1 vias
v30: diameter 0.45/0.45/0.45 (per signal layer), hole 0.15, L1 to L3 (Sign), 1 vias
v31: diameter 0.35/0.35/0.35 (per signal layer), hole 0.127, L1 to L3 (Sign), tented both sides, 1 vias
v32: diameter 0.45/0/0.45 (per signal layer), hole 0.15, L1 to L3 (Sign), tented both sides, 1 vias
v33: diameter 0.45/0/0.45 (per signal layer), hole 0.2, L14 (Sign) to L16, tented both sides, 1 vias
v34: diameter 0.35, hole 0.127, L2 (GND) to L3 (Sign), 1 vias

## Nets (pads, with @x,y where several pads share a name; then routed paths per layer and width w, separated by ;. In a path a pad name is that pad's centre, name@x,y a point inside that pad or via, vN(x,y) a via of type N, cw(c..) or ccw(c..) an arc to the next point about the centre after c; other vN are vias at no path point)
0.85V@40A_INA: C359.2 C360.2 C361.2 C362.2 C363.2 C364.2 C365.2 C366.2 C367.2 C368.2 C369.2 C370.2 C377.2 C378.2 C379.2 C380.2 C381.2 C382.2 C383.2 C384.2 C385.2 C386.2 C387.2 C388.2 L9.2 L10.2 R617.1 U72.10 | length 10.4
  L1 w0.164: 161.582,100.408 161.902,100.728 163.858,100.728
  L1 w0.912: R617.1@157.952,95.58 157.952,99.541 158.819,100.408 161.582,100.408
0V9@1A_REG3: C709.2 C710.2 R673.2 U1.A10 U1.C10 U1.F8 U1.H8 U1.M8 U1.P8 U70.11 U70.12
0V85@2A: C675.2 C746.2 FB45.2 U1.J23 U1.L23 | length 2.3
  L1 w0.254: 156.588,152.162 156.608,152.142 157.567,152.142 C675.2@157.587,152.122 FB45.2@157.587,150.837
1V0@1.5A: C505.2 C506.2 C507.2 C508.2 C509.2 C510.2 C511.2 C512.2 C513.2 C514.2 C555.2 R397.2 U39.6 U39.24 U39.31 U39.42 U51.8
1V8@0.5A_ADC_filtered: C705.2 C706.2 C749.2 C750.2 C757.1 C758.2 D28.3 FB38.1 FB40.1 FB42.1 R671.2 R694.1 R745.2 U1.K10 U1.L10 U1.M10 U1.N10 U1.P10 U1.T22 U1.U21 U1.V21 U1.V22 U70.14 U70.15
1V8@1.5A: C485.2 C486.2 C487.2 C488.2 C489.2 C490.2 C553.2 C561.2 C729.2 C730.2 R394.2 U39.13 U39.48 U45.28 U45.30 U50.8 U58.8
2V5@1.5A: C499.2 C500.2 C501.2 C502.2 C503.2 C504.2 C551.2 C782.2 C783.2 C784.2 C785.2 C786.2 C787.2 C788.2 C789.2 R391.2 R392.2 U8.B1 U8.R6 U9.B1 U9.R6 U10.B1 U10.R6 U11.B1 U11.R6 U39.3 U39.9 U49.8
3.3V_LN_1: C55.2 C56.2 C59.2 C60.2 C65.2 C66.2 C71.2 C72.2 C84.2 C85.2 C94.2 C95.2 C569.2 FB2.1 FB3.1 FB4.1 FB5.1 FB6.1 FB7.1 FB33.2 | length 0.1
  L1 w0.254: C569.2@294.834,196.4 C569.2@294.875,196.36
3.3V_PS_Config: C491.2 C492.2 C493.2 C494.2 C495.2 C496.2 C497.2 C498.2 C531.1 C547.2 C612.2 C613.2 C614.2 C615.2 C742.1 C743.2 C790.2 L17.2 R83.2 R84.2 R85.2 R86.2 R97.2 R98.2 R99.2 R106.1 R123.2 R216.1 R319.2 R320.2 R322.2 R323.2 R333.1 R336.1 R337.1 R338.1 R346.1 R347.1 R348.1 R349.2 R350.2 R351.2 R352.2 R353.1 R354.2 R355.1 R356.1 R357.2 R367.2 R368.2 R369.2 R370.2 R371.2 R372.2 R381.2 R382.2 R709.1 R710.2 R715.2 R716.2 R717.2 R718.2 R719.2 R737.2 U1.B22 U1.B27 U1.D18 U1.D23 U1.D28 U1.E21 U1.E26 U1.F19 U1.J18 U1.N20 U1.P18 U39.19 U39.30 U39.41 U43.1 U43.2 U43.7 U43.8 U43.15 U43.16 U44.1 U47.B3 U47.C4 U56.15 U68.3 U76.5 X6.1 X6.4 | length 21.9
  L1 w0.254: C614.2@235.147,260.761 235.42,261.034 235.42,261.439 235.57,261.588 247.122,261.588 249.13,259.58 R216.1@249.13,253.074
3.3V_Stable_1: C149.2 C150.2 C151.2 C152.2 C153.2 C154.2 C155.2 C156.2 C157.2 C158.2 C159.2 C160.2 C161.2 C181.2 C182.2 C183.2 C184.2 C185.2 C186.2 C187.2 C188.2 C189.2 C190.2 C191.2 C192.2 C193.2 C565_U_5V_to_3V33.2 C566_U_5V_to_3V33.2 C567_U_5V_to_3V33.2 R430_U_5V_to_3V33.2 R431_U_5V_to_3V33.2 U12.2 U12.5 U12.8 U12.11 U12.14 U12.17 U12.20 U12.23 U12.26 U12.29 U12.32 U12.35 U59_U_5V_to_3V33.8
3.3V_Stable_2: C166.2 C167.2 C168.2 C169.2 C170.2 C171.2 C172.2 C173.2 C174.2 C175.2 C176.2 C177.2 C178.2 C194.2 C195.2 C196.2 C197.2 C198.2 C199.2 C200.2 C201.2 C202.2 C203.2 C204.2 C205.2 C206.2 C565_U_5V_to_3V32.2 C566_U_5V_to_3V32.2 C567_U_5V_to_3V32.2 R430_U_5V_to_3V32.2 R431_U_5V_to_3V32.2 U13.2 U13.5 U13.8 U13.11 U13.14 U13.17 U13.20 U13.23 U13.26 U13.29 U13.32 U13.35 U59_U_5V_to_3V32.8
3.3V_Stable_3: C111.2 C112.2 C113.2 C114.2 C115.2 C116.2 C117.2 C118.2 C119.2 C120.2 C121.2 C122.2 C123.2 C128.2 C129.2 C130.2 C131.2 C132.2 C133.2 C134.2 C135.2 C136.2 C137.2 C138.2 C139.2 C140.2 C565_U_5V_to_3V31.2 C566_U_5V_to_3V31.2 C567_U_5V_to_3V31.2 R430_U_5V_to_3V31.2 R431_U_5V_to_3V31.2 U14.2 U14.5 U14.8 U14.11 U14.14 U14.17 U14.20 U14.23 U14.26 U14.29 U14.32 U14.35 U59_U_5V_to_3V31.8
3.3Vaux: C332.2 J27.2 J27.4 J27.12 J27.14 J27.16 J27.18 J27.62 J27.64 J27.66 U18.C2 U18.D1 U18.D2 U18.E1 U18.E2 U18.F1 U18.F2
3V3_Rail: C303_I2C_Bridge.2 C303_I2C_Bridge_2.2 C303_I2C_Bridge_3.2 C309_U_Pomiar_pradu_napiecia_1.2 C309_U_Pomiar_pradu_napiecia_2.2 C309_U_Pomiar_pradu_napiecia_3.2 C309_U_Pomiar_pradu_napiecia_4.2 C309_U_Pomiar_pradu_napiecia_5.2 C309_U_Pomiar_pradu_napiecia_6.2 C309_U_Pomiar_pradu_napiecia_7.2 C309_U_Pomiar_pradu_napiecia_8.2 C309_U_Pomiar_pradu_napiecia_9.2 C309_U_Pomiar_pradu_napiecia_10.2 C309_U_Pomiar_pradu_napiecia_11.2 C310.2 C311_I2C_Expander1.2 C311_I2C_Expander2.2 C311_I2C_Expander3.2 C311_I2C_Expander?.2 C311_I2C_Expander_10.2 C311_I2C_Expander_11.2 C311_I2C_Expander_12.2 C311_I2C_Expander_13.2 C311_I2C_Expander_14.2 C311_I2C_Expander_15.2 C311_I2C_Expander_16.2 C324.2 C331.2 C339.2 C545.2 C546.2 C550.2 C552.2 C554.2 C562.2 C585.2 C623.2 C654.2 C676.2 C707.2 C708.2 C721.2 C732.2 C735.2 C792.2 FB1_PCIE0.2 FB1_PCIE1.2 FB1_PCIE2.2 FB1_PCIE3.2 FB1_PCIE4.2 FB23.1 FB24.1 J1_PCIE0.6 J1_PCIE0.8 J1_PCIE0.10 J1_PCIE2.6 J1_PCIE2.8 J1_PCIE2.10 J1_PCIE4.6 J1_PCIE4.8 J1_PCIE4.10 J28.4 L1.1 L2.1 L3.1 L4.1 L5.1 L6.1 L7.1 L8.1 P12.1 R3_I2C_Bridge.2 R3_I2C_Bridge_2.2 R3_I2C_Bridge_3.2 R4_I2C_Bridge.2 R4_I2C_Bridge_2.2 R4_I2C_Bridge_3.2 R5_I2C_Bridge.2 R5_I2C_Bridge_2.2 R5_I2C_Bridge_3.2 R6_I2C_Bridge.2 R6_I2C_Bridge_2.2 R6_I2C_Bridge_3.2 R7_I2C_Bridge.2 R7_I2C_Bridge_2.2 R7_I2C_Bridge_3.2 R8_I2C_Bridge.2 R8_I2C_Bridge_2.2 R8_I2C_Bridge_3.2 R9_I2C_Bridge.2 R9_I2C_Bridge_2.2 R9_I2C_Bridge_3.2 R10_I2C_Bridge.2 R10_I2C_Bridge_2.2 R10_I2C_Bridge_3.2 R11.1 R13.1 R16.1 R29.2 R30.2 R65.2 R66.2 R67.2 R68.2 R71.2 R72.2 R124.2 R175.1 R179.1 R184.1 R188.1 R193.1 R197.1 R202.1 R206.1 R211.1 R219.1 R223_I2C_Bridge.2 R223_I2C_Bridge_2.2 R223_I2C_Bridge_3.2 R224_I2C_Bridge.2 R224_I2C_Bridge_2.2 R224_I2C_Bridge_3.2 R225_I2C_Bridge.2 R225_I2C_Bridge_2.2 R225_I2C_Bridge_3.2 R226_I2C_Bridge.2 R226_I2C_Bridge_2.2 R226_I2C_Bridge_3.2 R227_I2C_Bridge.2 R227_I2C_Bridge_2.2 R227_I2C_Bridge_3.2 R230.1 R231_SPI_bridge1.2 R231_SPI_bridge2.2 R233_SPI_bridge1.2 R233_SPI_bridge2.2 R233_SPI_bridge3.2 R236_SPI_bridge1.2 R236_SPI_bridge2.2 R236_SPI_bridge3.2 R238_SPI_bridge1.2 R240_SPI_bridge1.2 R240_SPI_bridge2.2 R241.2 R243.2 R252.2 R253.2 R281.2 R287.2 R376.2 R377.2 R378.2 R388.1 R425.2 R426.2 R427.2 R428.2 R429.2 R448_U_Pomiar_pradu_napiecia_3.2 R449.2 R451.2 R453.2 R455.2 R458.2 R462.2 R463.1 R468.1 R469.2 R471.2 R473.2 R475.2 R477.2 R479.2 R492.2 R494.2 R496.2 R500.2 R502.2 R504.2 R508.2 R510.2 R512.2 R516.2 R518.2 R520.2 R524.2 R526.2 R528.2 R538.2 R558_I2C_Bridge.2 R558_I2C_Bridge_2.2 R558_I2C_Bridge_3.2 R559_I2C_Bridge.2 R559_I2C_Bridge_2.2 R559_I2C_Bridge_3.2 R560_I2C_Bridge.2 R560_I2C_Bridge_2.2 R560_I2C_Bridge_3.2 R562.1 R566.1 R570.1 R574.1 R578.1 R582.1 R586.1 R590.1 R596.1 R599.2 R600.2 R602.1 R603.1 R604.1 R605.1 R606.1 R630.1 R632.2 R633.2 R634.2 R646.1 R649.1 R676.2 R691.1 R697.2 R699.2 R701.2 R703.2 R705.2 R707.2 R730.2 R731.2 R732.2 R733.2 R734.2 R738.2 R740.2 R742.2 R746.2 R747.2 R748.2 R749.2 R750.2 R751.2 R752.2 R753.2 R754.2 R755.2 R756.2 R757.2 R758.2 R760.2 R762.2 R832.1 R833.1 R834.1 R835.1 U3_I2C_Bridge.21 U3_I2C_Bridge_2.21 U3_I2C_Bridge_3.21 U15.15 U18.C3 U18.D3 U18.D4 U18.E3 U18.E4 U18.F3 U18.F4 U19.13 U19.16 U24_SPI_bridge1.1 U24_SPI_bridge1.7 U24_SPI_bridge1.8 U24_SPI_bridge1.15 U24_SPI_bridge1.16 U24_SPI_bridge2.1 U24_SPI_bridge2.7 U24_SPI_bridge2.8 U24_SPI_bridge2.15 U24_SPI_bridge2.16 U24_SPI_bridge3.1 U24_SPI_bridge3.7 U24_SPI_bridge3.8 U24_SPI_bridge3.16 U25_SPI_bridge1.1 U25_SPI_bridge1.7 U25_SPI_bridge1.8 U25_SPI_bridge1.15 U25_SPI_bridge1.16 U25_SPI_bridge2.1 U25_SPI_bridge2.7 U25_SPI_bridge2.8 U25_SPI_bridge2.15 U25_SPI_bridge2.16 U25_SPI_bridge3.1 U25_SPI_bridge3.7 U25_SPI_bridge3.8 U25_SPI_bridge3.15 U25_SPI_bridge3.16 U26_SPI_bridge1.1 U26_SPI_bridge1.7 U26_SPI_bridge1.8 U26_SPI_bridge1.15 U26_SPI_bridge1.16 U26_SPI_bridge2.1 U26_SPI_bridge2.7 U26_SPI_bridge2.8 U26_SPI_bridge2.15 U26_SPI_bridge2.16 U26_SPI_bridge3.1 U26_SPI_bridge3.7 U26_SPI_bridge3.8 U26_SPI_bridge3.15 U26_SPI_bridge3.16 U27_SPI_bridge1.1 U27_SPI_bridge1.7 U27_SPI_bridge1.8 U27_SPI_bridge1.15 U27_SPI_bridge1.16 U27_SPI_bridge2.1 U27_SPI_bridge2.7 U27_SPI_bridge2.8 U27_SPI_bridge2.16 U27_SPI_bridge3.1 U27_SPI_bridge3.7 U27_SPI_bridge3.8 U27_SPI_bridge3.16 U28_SPI_bridge1.1 U28_SPI_bridge1.7 U28_SPI_bridge1.8 U28_SPI_bridge1.15 U28_SPI_bridge1.16 U28_SPI_bridge2.1 U28_SPI_bridge2.7 U28_SPI_bridge2.8 U28_SPI_bridge2.15 U28_SPI_bridge2.16 U28_SPI_bridge3.1 U28_SPI_bridge3.7 U28_SPI_bridge3.8 U28_SPI_bridge3.16 U35_I2C_Expander1.5 U35_I2C_Expander2.5 U35_I2C_Expander3.5 U35_I2C_Expander?.5 U35_I2C_Expander_10.5 U35_I2C_Expander_11.5 U35_I2C_Expander_12.5 U35_I2C_Expander_13.5 U35_I2C_Expander_14.5 U35_I2C_Expander_15.5 U35_I2C_Expander_16.5 U36_U_Translator_I2C1.7 U36_U_Translator_I2C2.2 U36_U_Translator_I2C2.7 U36_U_Translator_I2C3.2 U36_U_Translator_I2C3.7 U36_U_Translator_I2C4.7 U45.32 U47.A4 U49.1 U49.2 U50.1 U50.2 U51.1 U51.2 U58.5 U63.3 U64_U_Pomiar_pradu_napiecia_1.6 U64_U_Pomiar_pradu_napiecia_2.6 U64_U_Pomiar_pradu_napiecia_3.6 U64_U_Pomiar_pradu_napiecia_3.8 U64_U_Pomiar_pradu_napiecia_3.9 U64_U_Pomiar_pradu_napiecia_4.6 U64_U_Pomiar_pradu_napiecia_5.6 U64_U_Pomiar_pradu_napiecia_6.6 U64_U_Pomiar_pradu_napiecia_7.6 U64_U_Pomiar_pradu_napiecia_8.6 U64_U_Pomiar_pradu_napiecia_9.6 U64_U_Pomiar_pradu_napiecia_10.6 U64_U_Pomiar_pradu_napiecia_11.6 U67.1 U68.1 U69.1 U69.2 U69.3 U69.15 U69.16 U70.1 U70.2 U70.4 U70.5 U72.6 U73.2 U74.5 U78.5 | length 53
  L1 w0.254: C554.2@181.782,123.677 C554.2@181.787,123.677 ; v9(204.604,41.265) 205.788,41.265 R287.2@205.838,41.314 ; U64_U_Pomiar_pradu_napiecia_4.6@266.005,173.619 U64_U_Pomiar_pradu_napiecia_4.6@266.014,173.609
  L14 (Sign) w0.254: 194.963,41.245 194.332,41.875 194.332,70.801 v9(201.672,78.14) ; 194.982,41.265 v9(204.604,41.265)
  L16 w0.254: R578.1@219.302,141.279 R582.1@221.208,141.279
  other v4: 220.243,141.279
5V_LN: C580.2 R443.2 R608.2 U12.42 U30.1 U30.5 U62.9 U62.10 X2.14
